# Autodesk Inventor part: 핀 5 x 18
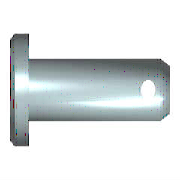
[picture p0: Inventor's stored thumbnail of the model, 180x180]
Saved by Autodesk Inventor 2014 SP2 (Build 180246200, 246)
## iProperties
Created: 2012-02
Part Number: 핀 5 x 18
Material: 강철
Description: 머리가 있는 클레비스 핀
Document SubType Name: Modeling
Standard: ISO 2341
Designer: test
Standard Revision: Second edition 1986-11-01
Standards Organization: ISO
Language: ko-KR
Size Designation: B - 5 x 18
Categories: <MemberInstance><Categories><Category DisplayName="조임쇠" InternalName="e4da775c-781d-43d5-af7c-5136215cf5a6" Mnemonic="FSTN"><Category DisplayName="핀" InternalNa
Density: 7.85 g/cm^3
Appearance: 강철
IsCustomPart: 1
Author: test
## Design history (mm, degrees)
sketch "스케치1"
  geometry: L1 (-1.6, 0)-(-1.6, 4); L2 (-1.6, 4)-(0, 4); L3 (0, 4)-(0, 2.5); L4 (0, 2.5)-(18, 2.5); L5 (18, 2.5)-(18, 0); L6 (-1.6, 0)-(18, 0); L7 (-4, 0)-(17, 0) reference; L8 (0, -0.98)-(0, 3.08) reference; C1 r 0.6 at (15.1, 0)
  constraints: 12 end point, 3 parallel, 2 collinear, 2 perpendicular, 1 centre point, 1 point on line, 1 vertical
  dimensions: "d0" = 5 diameter of L4 L6 (= NND); "d1" = 8 diameter of L2 L6 (= KOD); "d2" = 1.6 distance of L1.end L2.end (= KOH); "d3" = 18 distance of L3.end L4.end (= NLG); "d5" = 2.9 distance from line of L5 C1.centre (= DIST); "d6" = 1.2 diameter of C1 (= BOR)
revolve "본체" stored, may be unused: angle "d4" = 90 deg
extrude "구멍" cut sketch "스케치1" stored distance "d7" = 5 (= NND); taper "d8" = 0 deg
workaxis "Work Axis1"
workplane "Work Plane1"
body "Solid1"
chamfer "모따기1" distance "d9" = 1 (= PHH2); stored, may be unused: angle "d10" = 45 deg (= FAWI2), second distance "d16" = 1 (= PHH2)
chamfer "모따기2" distance "d11" = 2 (= PHH1); stored, may be unused: angle "d12" = 30 deg (= FAWI1), second distance "d17" = 2 (= PHH1)
other parameters: "PHH1" = 2 [user parameter; used in 2 equation terms], "PHH2" = 1 [user parameter; used in 2 equation terms], "KOD" = 8 [user parameter; used in 1 equation term], "KOH" = 1.6 [user parameter; used in 1 equation term], "NND" = 5 [user parameter; used in 2 equation terms], "FAWI1" = 30 deg [user parameter; used in 1 equation term], "FAWI2" = 45 deg [user parameter; used in 1 equation term], "DIST" = 2.9 [user parameter; used in 1 equation term], "BOR" = 1.2 [user parameter; used in 1 equation term], "NLG" = 18 [user parameter; used in 1 equation term], "d13" = 0, "d14" = 0, "d27" = 0, "d28" = 0, "d29" = 0, "d30" = 0, "d31" = 0
